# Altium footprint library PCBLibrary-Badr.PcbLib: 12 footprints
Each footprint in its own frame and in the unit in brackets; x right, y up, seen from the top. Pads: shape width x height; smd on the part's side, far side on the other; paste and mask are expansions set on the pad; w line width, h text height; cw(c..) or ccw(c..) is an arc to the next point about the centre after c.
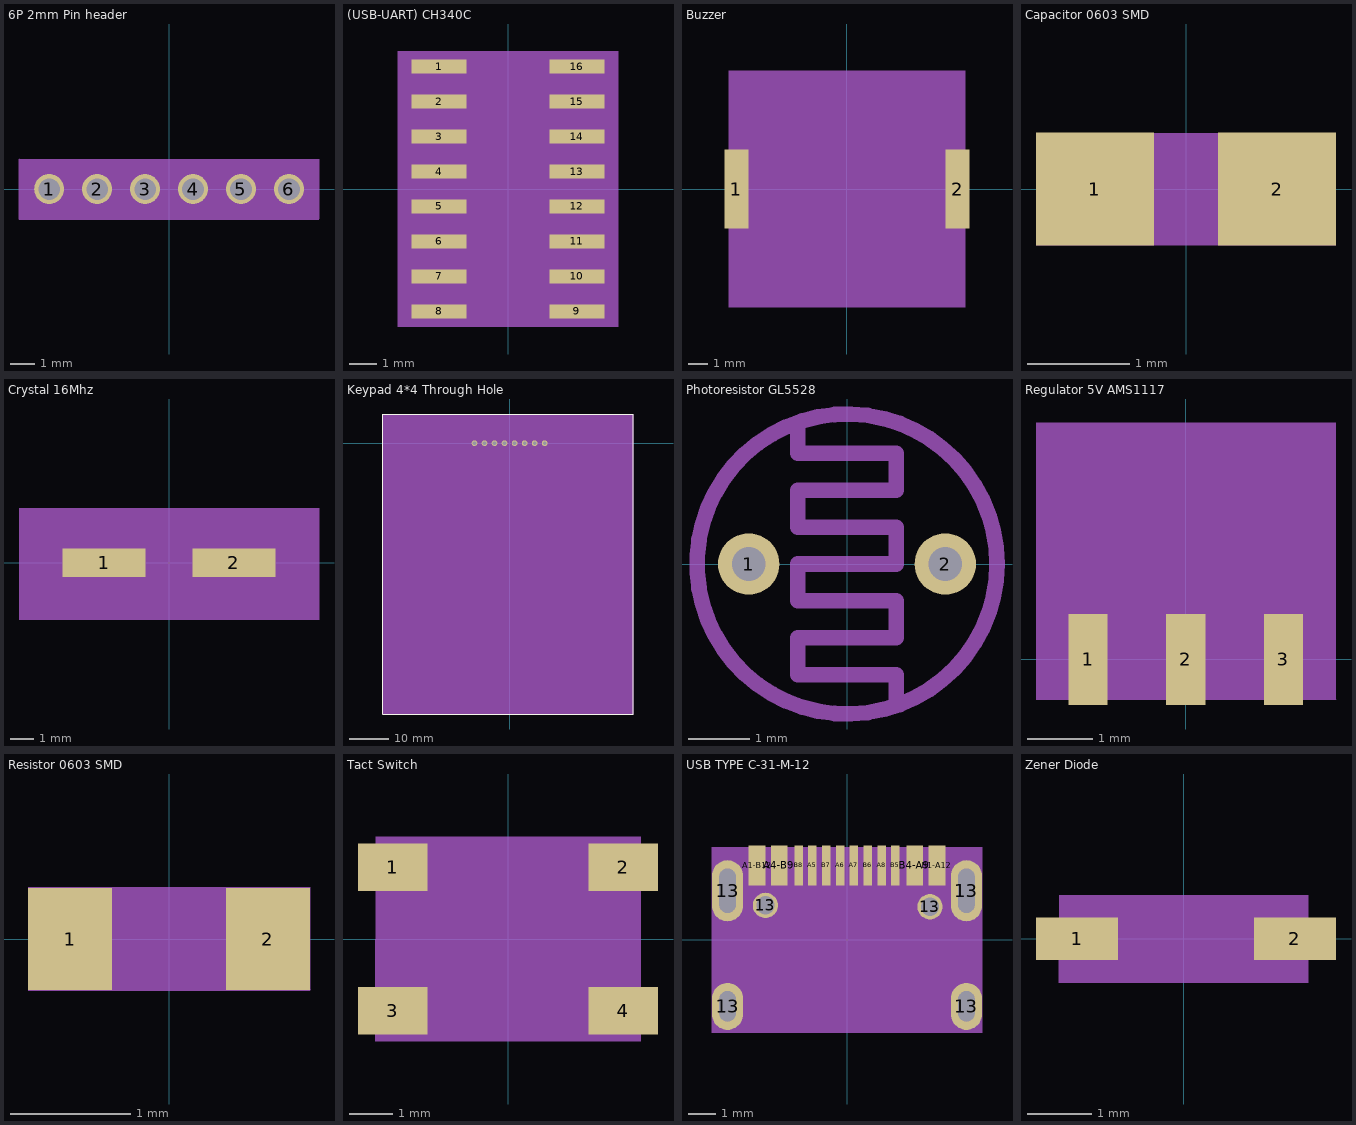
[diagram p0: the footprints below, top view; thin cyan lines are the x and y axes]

## 6P 2mm Pin header [mm]
pads (6):
  round 1.25 hole 0.9: 1(-5,0) 2(-3,0) 3(-1,0) 4(1,0) 5(3,0) 6(5,0)
Top Overlay:
  text ".Designator" at -1.3,1.794 h0.5
Mechanical 15:
  region: 6.246,1.243 6.252,1.236 6.252,-1.248 -6.25,-1.248 -6.256,-1.242 -6.244,-1.229 -6.244,1.255
  lines w0.05: -6.25,-1.25 6.25,-1.25 6.25,1.25 -6.25,1.25 -6.25,-1.25
3D body "User Library-MW-6M-2.STEP": height 6.17, standoff -3.23, extent -6.9,-1.5 7,3.3

## (USB-UART) CH340C [mm]
pads (16):
  rect 2x0.5 smd: 1(-2.5,4.445) 2(-2.5,3.175) 3(-2.5,1.905) 4(-2.5,0.635) 5(-2.5,-0.635) 6(-2.5,-1.905) 7(-2.5,-3.175) 8(-2.5,-4.445) 9(2.5,-4.445) 10(2.5,-3.175) 11(2.5,-1.905) 12(2.5,-0.635) 13(2.5,0.635) 14(2.5,1.905) 15(2.5,3.175) 16(2.5,4.445)
Top Overlay:
  text ".Designator" at -1.1,5.794 h0.5
Mechanical 15:
  region: -4,5 4,5 4,-5 -4,-5
3D body "CH340C-1.step": height 1.58, standoff 0, extent -3.117,-5 3.117,4.981

## Buzzer [mm]
pads (2):
  rect 1.2x4 smd: 1(-5.6,0) 2(5.6,0)
Top Overlay:
  text ".Designator" at -1.1,6.794 h0.5
Mechanical 15:
  region: -6,6 6,6 6,-6 -6,-6
3D body "PKLCS_472x472_MUR.step": height 3, standoff 0, extent -5.994,-5.994 5.994,5.994

## Capacitor 0603 SMD [mm]
pads (2):
  rect 1.15x1.1 smd: 1(-0.889,0) 2(0.889,0)
Top Overlay:
  text ".Designator" at -1.1,0.794 h0.5
Mechanical 15:
  region: -1.46,0.546 -1.464,0.542 -1.464,-0.548 1.454,-0.548 1.458,-0.552 1.458,0.546
3D body "User Library-cap_0603_lowprofile.step": height 0.6, standoff 0, extent -0.8,-0.4 0.8,0.4

## Crystal 16Mhz [mm]
pads (2):
  rect 3.5x1.2 smd: 1(-2.75,0) 2(2.75,0)
Top Overlay:
  text ".Designator" at -0.75,1.094 h0.5
Mechanical 15:
  region: -6.35,2.3 -6.35,-2.4 6.35,-2.4 6.35,2.3
3D body "User Library-HC49US.STEP": height 4.2, standoff 0, extent -6.35,-2.4 6.35,2.3

## Keypad 4*4 Through Hole [mil]
pads (8):
  round 57 / inner round 60 / far side round 57 hole 37 paste-99999 mask+0: 1(-350,0) 2(-250,0) 3(-150,0) 4(-50,0) 5(50,0) 6(150,0) 7(250,0) 8(350,0)
Top Overlay:
  lines w10: -1265.75,-2700.79 -1265.75,291.34 1234.25,291.34 1234.25,-2700.79 -1265.75,-2700.79
Mechanical 15:
  region: -1265.75,291.34 1234.25,291.34 1234.25,-2700.79 -1265.75,-2700.79
3D body "96bb2-006-fs-el.stp": height 389.96, standoff -215.04, extent -1250,-2550.39 1250,149.61

## Photoresistor GL5528 [mm]
pads (2):
  round 1 hole 0.55: 1(-1.6,0) 2(1.6,0)
Mechanical 15:
  circle w0.254: c0,0 r2.441
  lines w0.254: -0.8,2.2 -0.8,1.8 0.8,1.8 0.8,1.2 -0.8,1.2 -0.8,0.6 0.8,0.6 0.8,0 -0.8,0 -0.8,-0.6 0.8,-0.6 0.8,-1.2 -0.8,-1.2 -0.8,-1.8 0.8,-1.8 0.8,-2.2
3D body "User Library-photocell_v8.step": height 2.6, standoff -9.6, extent -2.55,-2.15 2.55,2.15

## Regulator 5V AMS1117 [mm]
pads (3):
  rect 0.6x1.4 smd: 1(-1.5,0) 2(0,0) 3(1.5,0)
Top Overlay:
  text ".Designator" at -1.5,1.65 h0.8
Mechanical 15:
  region: -2.295,-0.617 2.302,-0.617 2.307,-0.612 2.302,-0.607 2.302,3.631 -2.295,3.631 -2.3,3.626
3D body "SOT-89_STM.step": height 1.65, standoff 0, extent -2.298,-0.621 2.3,3.621

## Resistor 0603 SMD [mm]
pads (2):
  rect 0.7x0.85 smd: 1(-0.825,0) 2(0.825,0)
Top Overlay:
  text ".Designator" at -1,0.694 h0.5
Mechanical 15:
  region: -1.172,0.431 -1.174,0.43 -1.174,-0.432 1.172,-0.432 1.181,-0.423 1.177,-0.42 1.177,0.433
3D body "CircuitWorks-RESISTOR 0603.step": height 0.48, standoff -0.03, extent -0.8,-0.43 0.8,0.43

## Tact Switch [mm]
pads (4):
  rect 1.6x1.1 smd: 1(-2.65,1.65) 2(2.65,1.65) 3(-2.65,-1.65) 4(2.65,-1.65)
Top Overlay:
  text ".Designator" at -1,2.594 h0.5
Mechanical 15:
  region: -3.044,2.35 3.05,2.35 3.05,-2.35 -3.056,-2.35
3D body "xb-ts-1127-x.stp": height 1.6, standoff 0, extent -3,-2.34 3,2.34

## USB TYPE C-31-M-12 [mil]
pads (18):
  oval 44x67 / inner round 60 / far side oval 44x67 hole 23.62 slot 43.31 at 90 deg paste-99999 mask+0: 13(-170.08,-94.56) 13(170.08,-94.56)
  oval 44x87 / inner round 60 / far side oval 44x87 hole 23.62 slot 62.99 at 90 deg paste-99999 mask+0: 13(-170.08,70) 13(170.08,70)
  round 36 / inner round 60 / far side round 36 hole 26 paste-99999 mask-18: 13(-116.14,49.21) 13(118.11,47.24)
  rect 24x57 smd paste-28.5 mask-28.5: A1-B12(-127.96,106.06) A4-B9(-96.45,106.06) B1-A12(127.96,106.06) B4-A9(96.45,106.06)
  rect 12x57 smd paste-28.5 mask-28.5: A5(-49.22,106.06) A6(-9.85,106.06) A7(9.85,106.06) A8(49.22,106.06) B5(68.91,106.06) B6(29.54,106.06) B7(-29.54,106.06) B8(-68.91,106.06)
Top Overlay:
  text ".Designator" at -43.31,165.11 h19.68
Mechanical 15:
  region: -192.91,131.89 -192.91,-131.89 192.91,-131.89 192.91,131.89
3D body "TYPE-C 16P SMD.step": height 125.98, standoff -23.59, extent -224.41,-172.26 224.41,131.06

## Zener Diode [mil]
pads (2):
  rect 50x26 smd paste+0: 1(-65,0) 2(67.91,0)
Top Overlay:
  text ".Designator" at -70.87,57.09 h31.5
Mechanical 13:
  lines w1: -75.79,-10.83 -75.79,10.83 -56.1,10.83 -56.1,-10.83 -75.79,-10.83 ; 56.1,-10.83 56.1,10.83 75.79,10.83 75.79,-10.83 56.1,-10.83
Mechanical 15:
  region: -75.87,26.57 75.95,26.57 75.95,-26.71 75.85,-26.82 75.75,-26.72 -76.06,-26.72
3D body "SOD123_DIO.step": height 32.09, standoff 0, extent -75.79,-26.57 75.79,26.57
